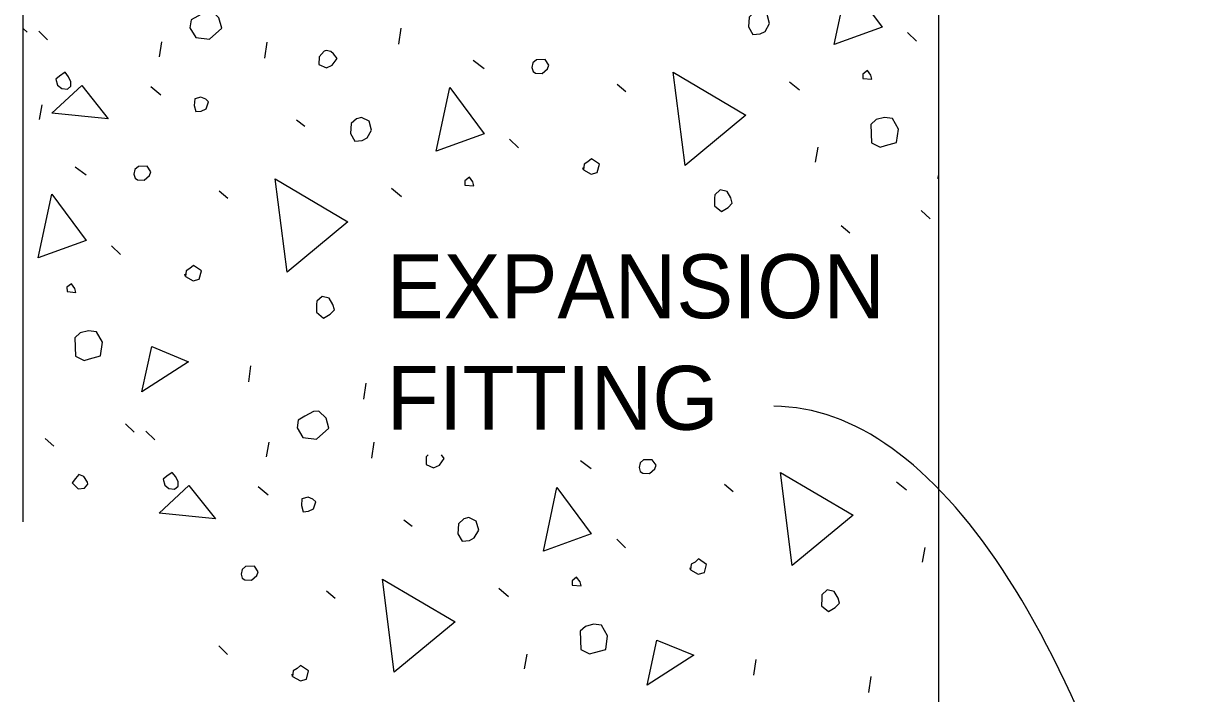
# Model space of a CAD drawing. Extents: x -1660015.2 to -1659984.9, y 2580594.2 to 2580616.7.
# Drawn here: x -1659992.683 to -1659989.941, y 2580609.587 to 2580611.174 of the extents above; entities that cross this region are included whole.
import ezdxf

# ---------------------------------------------------------------- set-up
doc = ezdxf.new("R2010")
doc.units = 0
for name, color, linetype in [('Miscellaneous', 7, 'Continuous'), ('Miscellaneous3', 7, 'Continuous'), ('SheetLines_dp', 7, 'Continuous')]:
    doc.layers.add(name, color=color, linetype=linetype)

msp = doc.modelspace()

# ---------------------------------------------------------------- linework, layer by layer
at = {"layer": 'Miscellaneous'}
for p, q in [((-1659992.6826, 2580611.1615), (-1659992.6735, 2580611.1527)), ((-1659992.6456, 2580611.155), (-1659992.6247, 2580611.1347)), ((-1659991.7937, 2580611.1245), (-1659991.7882, 2580611.1622)), ((-1659990.5898, 2580611.152), (-1659990.5688, 2580611.1317)), ((-1659992.3602, 2580611.0943), (-1659992.3541, 2580611.1296)), ((-1659992.1109, 2580611.0912), (-1659992.1055, 2580611.1289)), ((-1659991.6178, 2580611.0862), (-1659991.592, 2580611.0672)), ((-1659990.8692, 2580611.0357), (-1659990.8458, 2580611.0161)), ((-1659992.3802, 2580611.0242), (-1659992.3568, 2580611.0046)), ((-1659991.2766, 2580611.0301), (-1659991.2563, 2580611.0122)), ((-1659992.6439, 2580610.9458), (-1659992.6378, 2580610.9811)), ((-1659992.0357, 2580610.9457), (-1659992.016, 2580610.9303)), ((-1659991.5316, 2580610.8996), (-1659991.5106, 2580610.8794)), ((-1659990.8078, 2580610.8451), (-1659990.8017, 2580610.8804)), ((-1659992.5596, 2580610.8338), (-1659992.5338, 2580610.8149)), ((-1659992.2184, 2580610.7777), (-1659992.1981, 2580610.7599)), ((-1659991.811, 2580610.7834), (-1659991.7876, 2580610.7637)), ((-1659990.5572, 2580610.7311), (-1659990.5363, 2580610.7108)), ((-1659990.7471, 2580610.6957), (-1659990.7267, 2580610.6779)), ((-1659992.4733, 2580610.6473), (-1659992.4524, 2580610.627)), ((-1659992.1489, 2580610.3253), (-1659992.1435, 2580610.363)), ((-1659991.8766, 2580610.2844), (-1659991.8711, 2580610.3221)), ((-1659992.4408, 2580610.2264), (-1659992.4198, 2580610.2061)), ((-1659992.6306, 2580610.191), (-1659992.6103, 2580610.1732)), ((-1659992.392, 2580610.2084), (-1659992.371, 2580610.1881)), ((-1659992.1065, 2580610.1477), (-1659992.1005, 2580610.183)), ((-1659991.8572, 2580610.1446), (-1659991.8518, 2580610.1823)), ((-1659991.3641, 2580610.1396), (-1659991.3383, 2580610.1206)), ((-1659992.1266, 2580610.0776), (-1659992.1032, 2580610.058)), ((-1659991.023, 2580610.0835), (-1659991.0027, 2580610.0656)), ((-1659990.6156, 2580610.0891), (-1659990.5922, 2580610.0695)), ((-1659991.782, 2580609.9991), (-1659991.7624, 2580609.9837)), ((-1659991.2779, 2580609.953), (-1659991.257, 2580609.9328)), ((-1659990.5541, 2580609.8985), (-1659990.5481, 2580609.9338)), ((-1659991.9648, 2580609.8311), (-1659991.9444, 2580609.8133)), ((-1659991.5573, 2580609.8368), (-1659991.534, 2580609.8171)), ((-1659992.2197, 2580609.7007), (-1659992.1987, 2580609.6804)), ((-1659991.4959, 2580609.6462), (-1659991.4898, 2580609.6814)), ((-1659990.9535, 2580609.631), (-1659990.9481, 2580609.6687)), ((-1659990.6812, 2580609.5901), (-1659990.6757, 2580609.6278))]:
    msp.add_line(p, q, dxfattribs=at)
for points in [[(-1659990.7633, 2580611.1236), (-1659990.7313, 2580611.2745), (-1659990.65, 2580611.1643), (-1659990.7633, 2580611.1236)], [(-1659992.288, 2580611.1628), (-1659992.2742, 2580611.1406), (-1659992.242, 2580611.1363), (-1659992.2127, 2580611.1623), (-1659992.2192, 2580611.1864), (-1659992.2365, 2580611.2025), (-1659992.2492, 2580611.2017), (-1659992.2696, 2580611.191), (-1659992.2852, 2580611.1817), (-1659992.288, 2580611.1628)], [(-1659990.9646, 2580611.1887), (-1659990.966, 2580611.1651), (-1659990.956, 2580611.147), (-1659990.9384, 2580611.1492), (-1659990.927, 2580611.1548), (-1659990.9164, 2580611.1732), (-1659990.9222, 2580611.1949), (-1659990.9399, 2580611.2031), (-1659990.952, 2580611.1999), (-1659990.9646, 2580611.1887)], [(-1659991.9824, 2580611.0946), (-1659991.9827, 2580611.0764), (-1659991.965, 2580611.0682), (-1659991.9511, 2580611.0745), (-1659991.9399, 2580611.0905), (-1659991.9479, 2580611.1012), (-1659991.9547, 2580611.1072), (-1659991.9656, 2580611.1094), (-1659991.9705, 2580611.1081), (-1659991.9824, 2580611.0946)], [(-1659991.476, 2580611.0595), (-1659991.4699, 2580611.0559), (-1659991.4541, 2580611.055), (-1659991.4416, 2580611.0661), (-1659991.4387, 2580611.0746), (-1659991.4474, 2580611.0878), (-1659991.468, 2580611.0875), (-1659991.4764, 2580611.0801), (-1659991.4786, 2580611.0691), (-1659991.476, 2580611.0595)], [(-1659990.6953, 2580611.0435), (-1659990.674, 2580611.0414), (-1659990.6766, 2580611.0511), (-1659990.6847, 2580611.0619), (-1659990.6955, 2580611.0538), (-1659990.6953, 2580611.0435)], [(-1659992.601, 2580611.0272), (-1659992.5912, 2580611.0195), (-1659992.5778, 2580611.0179), (-1659992.5694, 2580611.0253), (-1659992.5696, 2580611.0356), (-1659992.5753, 2580611.047), (-1659992.5833, 2580611.0578), (-1659992.5965, 2580611.0491), (-1659992.6049, 2580611.0417), (-1659992.601, 2580611.0272)], [(-1659991.1163, 2580610.8375), (-1659991.1443, 2580611.0578), (-1659990.9722, 2580610.9564), (-1659991.1163, 2580610.8375)], [(-1659992.6145, 2580610.9615), (-1659992.544, 2580611.0269), (-1659992.4814, 2580610.9479), (-1659992.6145, 2580610.9615)], [(-1659991.7051, 2580610.8713), (-1659991.6731, 2580611.0222), (-1659991.5918, 2580610.912), (-1659991.7051, 2580610.8713)], [(-1659992.2776, 2580610.9793), (-1659992.2737, 2580610.9648), (-1659992.261, 2580610.9656), (-1659992.2496, 2580610.9713), (-1659992.2438, 2580610.9883), (-1659992.2505, 2580610.9943), (-1659992.2622, 2580610.9989), (-1659992.2766, 2580610.9951), (-1659992.2776, 2580610.9793)], [(-1659990.6765, 2580610.9346), (-1659990.6751, 2580610.891), (-1659990.6544, 2580610.881), (-1659990.6423, 2580610.8843), (-1659990.6157, 2580610.8914), (-1659990.6114, 2580610.9236), (-1659990.6258, 2580610.9482), (-1659990.6446, 2580610.9509), (-1659990.6639, 2580610.9458), (-1659990.6765, 2580610.9346)], [(-1659991.9063, 2580610.9364), (-1659991.9078, 2580610.9127), (-1659991.8978, 2580610.8947), (-1659991.8802, 2580610.8968), (-1659991.8688, 2580610.9025), (-1659991.8582, 2580610.9208), (-1659991.864, 2580610.9426), (-1659991.8817, 2580610.9508), (-1659991.8938, 2580610.9475), (-1659991.9063, 2580610.9364)], [(-1659991.3569, 2580610.8274), (-1659991.3385, 2580610.8168), (-1659991.324, 2580610.8207), (-1659991.3189, 2580610.8402), (-1659991.3379, 2580610.8532), (-1659991.3463, 2580610.8458), (-1659991.3553, 2580610.8408), (-1659991.3569, 2580610.8274), (-1659991.3582, 2580610.8322)], [(-1659992.4178, 2580610.8071), (-1659992.4117, 2580610.8036), (-1659992.3959, 2580610.8026), (-1659992.3834, 2580610.8138), (-1659992.3805, 2580610.8223), (-1659992.3892, 2580610.8355), (-1659992.4098, 2580610.8351), (-1659992.4182, 2580610.8277), (-1659992.4204, 2580610.8168), (-1659992.4178, 2580610.8071)], [(-1659990.5179, 2580610.8063), (-1659990.5159, 2580610.8155)], [(-1659992.0581, 2580610.5851), (-1659992.0861, 2580610.8054), (-1659991.914, 2580610.704), (-1659992.0581, 2580610.5851)], [(-1659991.6371, 2580610.7911), (-1659991.6158, 2580610.7891), (-1659991.6184, 2580610.7987), (-1659991.6265, 2580610.8095), (-1659991.6372, 2580610.8014), (-1659991.6371, 2580610.7911)], [(-1659990.5159, 2580610.8076), (-1659990.5179, 2580610.8063)], [(-1659992.6469, 2580610.6189), (-1659992.6149, 2580610.7698), (-1659992.5336, 2580610.6596), (-1659992.6469, 2580610.6189)], [(-1659991.0465, 2580610.7604), (-1659991.0468, 2580610.7422), (-1659991.0302, 2580610.7286), (-1659991.0146, 2580610.7379), (-1659991.0045, 2580610.7484), (-1659991.0077, 2580610.7605), (-1659991.017, 2580610.7761), (-1659991.0335, 2580610.7795), (-1659991.046, 2580610.7683), (-1659991.0465, 2580610.7604)], [(-1659992.2987, 2580610.575), (-1659992.2803, 2580610.5644), (-1659992.2658, 2580610.5683), (-1659992.2607, 2580610.5878), (-1659992.2797, 2580610.6008), (-1659992.2881, 2580610.5934), (-1659992.2971, 2580610.5884), (-1659992.2987, 2580610.575), (-1659992.3, 2580610.5799)], [(-1659992.5788, 2580610.5388), (-1659992.5576, 2580610.5367), (-1659992.5602, 2580610.5464), (-1659992.5682, 2580610.5572), (-1659992.579, 2580610.5491), (-1659992.5788, 2580610.5388)], [(-1659991.9883, 2580610.5081), (-1659991.9886, 2580610.4899), (-1659991.972, 2580610.4762), (-1659991.9564, 2580610.4856), (-1659991.9462, 2580610.4961), (-1659991.9495, 2580610.5081), (-1659991.9588, 2580610.5237), (-1659991.9753, 2580610.5271), (-1659991.9878, 2580610.516), (-1659991.9883, 2580610.5081)], [(-1659992.56, 2580610.4299), (-1659992.5587, 2580610.3863), (-1659992.5379, 2580610.3763), (-1659992.5258, 2580610.3796), (-1659992.4993, 2580610.3867), (-1659992.495, 2580610.4189), (-1659992.5093, 2580610.4435), (-1659992.5282, 2580610.4463), (-1659992.5475, 2580610.4411), (-1659992.56, 2580610.4299)], [(-1659992.4014, 2580610.3016), (-1659992.3784, 2580610.4087), (-1659992.291, 2580610.3726), (-1659992.4014, 2580610.3016)], [(-1659992.0343, 2580610.2162), (-1659992.0206, 2580610.194), (-1659991.9884, 2580610.1897), (-1659991.9591, 2580610.2157), (-1659991.9656, 2580610.2398), (-1659991.9828, 2580610.2559), (-1659991.9955, 2580610.2551), (-1659992.016, 2580610.2444), (-1659992.0316, 2580610.2351), (-1659992.0343, 2580610.2162)], [(-1659991.7287, 2580610.148), (-1659991.729, 2580610.1298), (-1659991.7113, 2580610.1216), (-1659991.6975, 2580610.1279), (-1659991.6862, 2580610.1439), (-1659991.6929, 2580610.1528)], [(-1659991.7245, 2580610.1528), (-1659991.7287, 2580610.148)], [(-1659991.2224, 2580610.1129), (-1659991.2163, 2580610.1093), (-1659991.2005, 2580610.1084), (-1659991.1879, 2580610.1195), (-1659991.185, 2580610.128), (-1659991.1938, 2580610.1412), (-1659991.2144, 2580610.1409), (-1659991.2227, 2580610.1335), (-1659991.225, 2580610.1225), (-1659991.2224, 2580610.1129)], [(-1659992.5664, 2580610.0866), (-1659992.5522, 2580610.0723), (-1659992.5371, 2580610.0738), (-1659992.5293, 2580610.0836), (-1659992.5306, 2580610.0884), (-1659992.5394, 2580610.1016), (-1659992.551, 2580610.1063), (-1659992.5587, 2580610.0964), (-1659992.5664, 2580610.0866)], [(-1659992.3474, 2580610.0806), (-1659992.3375, 2580610.0729), (-1659992.3242, 2580610.0713), (-1659992.3158, 2580610.0787), (-1659992.316, 2580610.089), (-1659992.3216, 2580610.1004), (-1659992.3297, 2580610.1112), (-1659992.3429, 2580610.1025), (-1659992.3513, 2580610.0951), (-1659992.3474, 2580610.0806)], [(-1659990.8627, 2580609.8909), (-1659990.8906, 2580610.1112), (-1659990.7185, 2580610.0097), (-1659990.8627, 2580609.8909)], [(-1659992.3608, 2580610.0149), (-1659992.2904, 2580610.0803), (-1659992.2278, 2580610.0013), (-1659992.3608, 2580610.0149)], [(-1659991.4515, 2580609.9246), (-1659991.4195, 2580610.0756), (-1659991.3382, 2580609.9654), (-1659991.4515, 2580609.9246)], [(-1659992.0239, 2580610.0327), (-1659992.0201, 2580610.0182), (-1659992.0073, 2580610.019), (-1659991.9959, 2580610.0246), (-1659991.9901, 2580610.0417), (-1659991.9969, 2580610.0477), (-1659992.0085, 2580610.0523), (-1659992.023, 2580610.0484), (-1659992.0239, 2580610.0327)], [(-1659991.6527, 2580609.9898), (-1659991.6541, 2580609.9661), (-1659991.6441, 2580609.9481), (-1659991.6266, 2580609.9502), (-1659991.6151, 2580609.9559), (-1659991.6045, 2580609.9742), (-1659991.6104, 2580609.996), (-1659991.6281, 2580610.0041), (-1659991.6401, 2580610.0009), (-1659991.6527, 2580609.9898)], [(-1659992.1642, 2580609.8605), (-1659992.158, 2580609.857), (-1659992.1423, 2580609.856), (-1659992.1297, 2580609.8671), (-1659992.1268, 2580609.8757), (-1659992.1355, 2580609.8889), (-1659992.1561, 2580609.8885), (-1659992.1645, 2580609.8811), (-1659992.1668, 2580609.8702), (-1659992.1642, 2580609.8605)], [(-1659991.1033, 2580609.8808), (-1659991.0849, 2580609.8702), (-1659991.0704, 2580609.8741), (-1659991.0653, 2580609.8935), (-1659991.0843, 2580609.9066), (-1659991.0927, 2580609.8991), (-1659991.1017, 2580609.8941), (-1659991.1033, 2580609.8808), (-1659991.1046, 2580609.8856)], [(-1659991.8045, 2580609.6385), (-1659991.8324, 2580609.8588), (-1659991.6603, 2580609.7574), (-1659991.8045, 2580609.6385)], [(-1659991.3834, 2580609.8445), (-1659991.3622, 2580609.8425), (-1659991.3648, 2580609.8521), (-1659991.3728, 2580609.8629), (-1659991.3836, 2580609.8548), (-1659991.3834, 2580609.8445)], [(-1659990.7929, 2580609.8138), (-1659990.7932, 2580609.7956), (-1659990.7766, 2580609.782), (-1659990.7609, 2580609.7913), (-1659990.7508, 2580609.8018), (-1659990.754, 2580609.8139), (-1659990.7634, 2580609.8295), (-1659990.7798, 2580609.8329), (-1659990.7924, 2580609.8217), (-1659990.7929, 2580609.8138)], [(-1659991.3646, 2580609.7357), (-1659991.3633, 2580609.692), (-1659991.3425, 2580609.6821), (-1659991.3304, 2580609.6853), (-1659991.3039, 2580609.6924), (-1659991.2995, 2580609.7247), (-1659991.3139, 2580609.7493), (-1659991.3327, 2580609.752), (-1659991.3521, 2580609.7468), (-1659991.3646, 2580609.7357)], [(-1659991.206, 2580609.6074), (-1659991.1829, 2580609.7145), (-1659991.0956, 2580609.6784), (-1659991.206, 2580609.6074)], [(-1659992.045, 2580609.6284), (-1659992.0267, 2580609.6178), (-1659992.0122, 2580609.6217), (-1659992.007, 2580609.6412), (-1659992.0261, 2580609.6542), (-1659992.0344, 2580609.6468), (-1659992.0434, 2580609.6418), (-1659992.045, 2580609.6284), (-1659992.0463, 2580609.6333)]]:
    msp.add_lwpolyline(points, dxfattribs=at)
at = {"layer": 'Miscellaneous3'}
for p, q in [((-1659992.6826, 2580609.9942), (-1659992.6826, 2580612.362)), ((-1659990.5159, 2580608.776), (-1659990.5159, 2580612.362))]:
    msp.add_line(p, q, dxfattribs=at)
at = {"layer": 'SheetLines_dp'}
msp.add_ellipse((-1659990.9235, 2580606.5865), major_axis=(-0.0172, -3.681), ratio=0.331804, start_param=2.220726, end_param=3.141608, dxfattribs=at)

# ---------------------------------------------------------------- texts
for s, p in [('EXPANSION', (-1659991.8227, 2580610.476)), ('FITTING', (-1659991.8227, 2580610.212))]:
    msp.add_text(s, height=0.1512, dxfattribs=at).set_placement(p)

doc.saveas('drawing.dxf')
